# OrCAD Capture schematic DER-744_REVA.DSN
size B; title: DER 744 Rev A
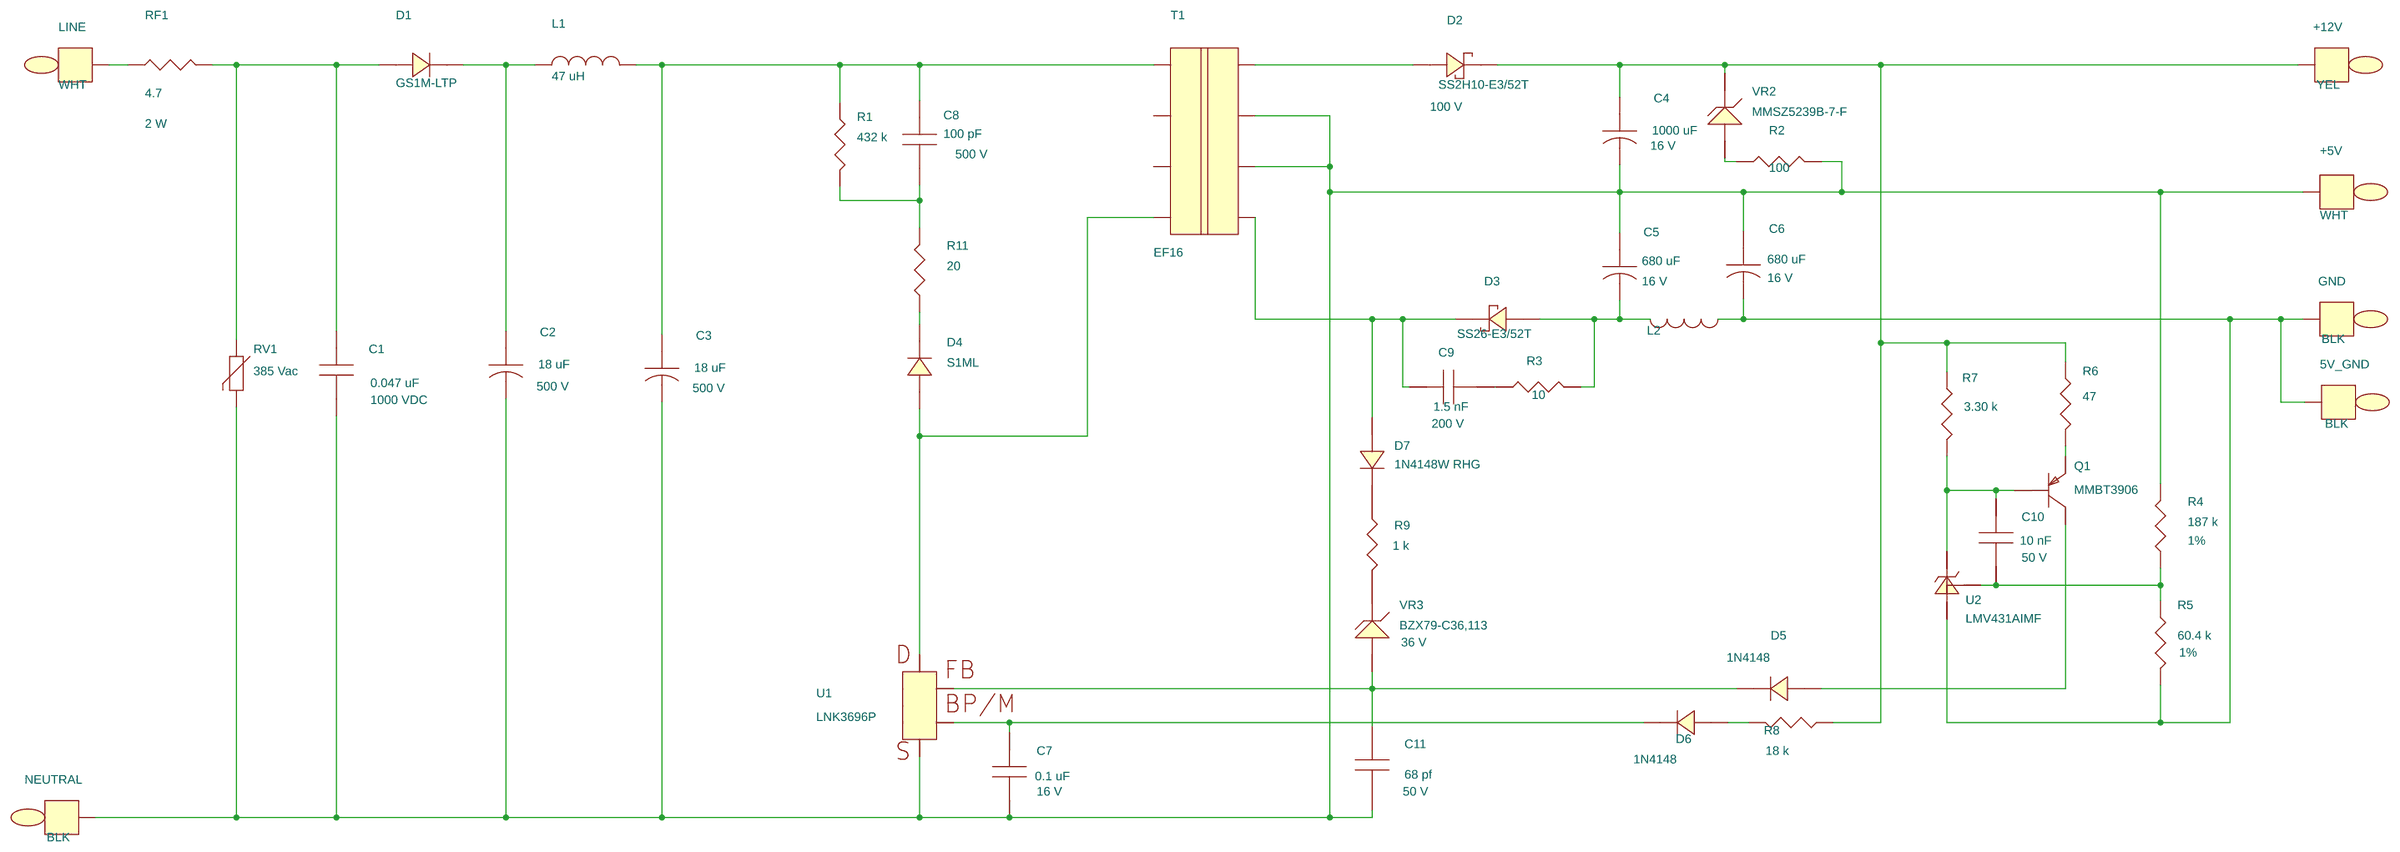
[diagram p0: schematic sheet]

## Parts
5V_GND  BLK  [pitpkeystone100x100]
+5V  WHT  [pitpkeystone100x100]
+12V  YEL  [pitpkeystone100x100]
C1  0.047 uF  [pinpcaprad18x6ls15mm040]
C2  18 uF  [pipolcapclyd630ls300040]
C3  18 uF  [pipolcapclyd630ls300040]
C4  1000 uF  [pipolcapclyd320ls140030]
C5  680 uF  [pi_polcap_d8h22ls3p5mmd030H]
C6  680 uF  [pi_polcap_d8h22ls3p5mmd030H]
C7  0.1 uF  [pismc0805]
C8  100 pF  [pismc1206]
C9  1.5 nF  [pismc0805]
C10  10 nF  [pismc0805]
C11  68 pf  [pismc0805]
D1  GS1M-LTP  [pismdo214ac12]
D2  SS2H10-E3/52T  [pismsmb]
D3  SS26-E3/52T  [pismdo214ac12]
D4  S1ML  [pi_sm_sod-123_12]
D5  1N4148  [pidv200x080x030do35]
D6  1N4148  [pidv200x080x030do35]
D7  1N4148W RHG  [pi_sm_sod-123_12]
GND  BLK  [pitpkeystone100x100]
L1  47 uH  [pichoketokinvd345h453ls197d030]
L2  50 Ohm @ 100MHz  [pismr1206]
LINE  WHT  [pitpkeystone125x125]
NEUTRAL  BLK  [pitpkeystone125x125]
Q1  MMBT3906  [pismsot23123_1]
R1  432 k  [pismr1206]
R2  100  [pismr0805]
R3  10  [pismr0805]
R4  187 k  [pi14wvresd100ls100d030]
R5  60.4 k  [pismr0805]
R6  47  [pismr0805]
R7  3.30 k  [pismr0805]
R8  18 k  [pismr0805]
R9  1 k  [pismr0805]
R11  20  [pismr1206]
RF1  4.7  [PI_2W_VRES240LS200D040]
RV1  385 Vac  [pi_disc_530x315ls295x70d040]
T1  EF16  [pibobbinEF16V8P]
U1  LNK3696P  [piicdip8cshort5678]
U2  LMV431AIMF  [pismsot23132]
VR2  MMSZ5239B-7-F  [pi_sm_sod-123_12]
VR3  BZX79-C36,113  [pidv200x080x030do35]

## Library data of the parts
5V_GND GND = TESTPOINT: Part Number: 35-00079-00
+5V = TESTPOINT: Part Number: 35-00081-00
+12V = TESTPOINT: Part Number: 35-00404-00
C1 = CAP_NP: Disp_Voltage: 1000 VDC; Part Number: 20-09149-00; Voltage: 1000 VDC (440VAC)
C2 C3 = CAP_POL: Disp_Voltage: 500 V; Part Number: 20-09150-00; Voltage: 500 V
C4 = CAP_POL: ALT_SYMBOLS: pipolcapclyd320ls140d30h750; Disp_Voltage: 16 V; FPLIST: pipolcapclyd320ls140030,pipolcapclyd320ls140d30h750; Part Number: 20-08710-00; Voltage: 16 V
C5 C6 = CAP_POL: ALT_SYMBOLS: pi_polcap_d8ls3p5mmd030; Disp_Voltage: 16 V; FPLIST: pi_polcap_d8h22ls3p5mmd030H,pi_polcap_d8ls3p5mmd030; Part Number: 20-09148-00; Voltage: 16V
C7 = CAP_NP: Disp_Voltage: 16 V; Part Number: 20-09164-00; Voltage: 16 V
C8 = CAP_NP: Disp_Voltage: 500 V; Part Number: 20-09163-00; Voltage: 500 V
C9 = CAP_NP: Disp_Voltage: 200 V; Part Number: 20-01150-00; Voltage: 200 V
C10 = CAP_NP: Disp_Voltage: 50 V; Part Number: 20-00965-00; Voltage: 50 V
C11 = CAP_NP: Disp_Voltage: 50 V; Part Number: 24-08976-00; Voltage: 50 V
D1 = DIODE: Part Number: 15-01111-00
D2 = DIODE_SCHOTTKY: Disp_Voltage: 100 V; Part Number: 15-00995-00
D3 = DIODE_SCHOTTKY: FPLIST: pismdo214aa12,pismdo214ac12; Part Number: 15-00366-00
D4 = DIODE: Part Number: 15-01027-00
D5 D6 = DIODE: ALT_SYMBOLS: pidax375x070030do35,pidv100x080x030do35; FPLIST: pidv200x080x030do35,pidax375x070030do35,pidv100x080x030do35; Part Number: 15-00083-00
D7 = DIODE: ALT_SYMBOLS: pi_sm_sod-123_12_1; FPLIST: pi_sm_sod-123_12,pi_sm_sod-123_12_1; Part Number: 15-01269-00
L1 = INDUCTOR: Part Number: 30-04098-00
L2 = INDUCTOR_BEAD: Part Number: 30-00491-00
LINE = TESTPOINT: Part Number: 35-00044-00
NEUTRAL = TESTPOINT: Part Number: 35-00042-00
Q1 = PNP_BEC: Part Number: 55-00049-00
R1 = R: Disp_Tol: 1%; Part Number: 05-00446-00
R2 = R: Part Number: 05-01495-00
R3 = R: Part Number: 05-01471-00
R4 = R: ALT_SYMBOLS: pi14wvresd100ls200d030,pi14wresd100ls400d030,pi14wresd100ls500d030; Disp_Tol: 1%; FPLIST: pi14wvresd100ls100d030,pi14wvresd100ls200d030,pi14wresd100ls400d030,pi14wresd100ls500d030; Part Number: 05-02194-00
R5 = R: Disp_Tol: 1%; Part Number: 05-00759-00
R6 = R: Part Number: 05-01487-00
R7 = R: Disp_Tol: 1%; Part Number: 05-05369-00
R8 = R: Part Number: 05-01549-00
R9 = R: Part Number: 05-01519-00
R11 = R: Part Number: 05-01311-00
RF1 = R: ALT_SYMBOLS: pi_2w_res6mmls15mmd040; Disp_Power: 2 W; FPLIST: PI_2W_VRES240LS200D040,pi_2w_res6mmls15mmd040; Part Number: 05-05550-00
RV1 = VARISTOR: ALT_SYMBOLS: pi_np_ycap_rad540ls400d040_h,pi_2w_resd145ls455d040; FPLIST: pi_disc_530x315ls295x70d040,pi_np_ycap_rad540ls400d040_h,pi_2w_resd145ls455d040; Part Number: 85-00021-00
T1 = BEF16_8PINS_GENERIC: Part Number: 25-01138-00
U1 = LNK3696: Part Number: 10-01089-00
U2 = TL431_SOT-23_RCA: Part Number: 45-00019-00
VR2 = DIODE_ZENER: Part Number: 15-01087-00
VR3 = DIODE_ZENER: ALT_SYMBOLS: pidax375x070030do35; Disp_Voltage: 36 V; FPLIST: pidv200x080x030do35,pidax375x070030do35; Part Number: 15-00270-00

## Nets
N00739: C7.1 D6.1 U1.1(BP/M)
N00834: D4.2 T1.4 U1.4(D)
N00928: C3.1 C8.1 L1.2 R1.1 T1.1
N01202: C8.2 R1.2 R11.2
N01422: C2.1 D1.1 L1.1
N01526: +5V.1 C1.2 C2.2 C3.2 C4.2 C5.1 C6.1 C7.2 C11.2 NEUTRAL.1 R2.2 R4.2 RV1.2 T1.6 T1.7 U1.5(S)
N01677: C1.1 D1.2 RF1.2 RV1.1
N02556: LINE.1 RF1.1
N02791: +12V.1 C4.1 D2.1 R6.1 R7.1 R8.1 VR2.1
N02906: C9.2 R3.1
N02910: C5.2 D3.2 L2.2 R3.2
N02953: C9.1 D3.1 D7.2 T1.5
N03528: 5V_GND.1 C6.2 GND.1 L2.1 R5.2 U2.3(A)
N03748: R2.1 VR2.2
N05482: C10.1 Q1.1(BASE) R7.2 U2.2(C)
N05581: C10.2 R4.1 R5.1 U2.1(VREF)
N08747: Q1.2(EMITTER) R6.2
N09276: C11.1 D5.1 U1.2(FB) VR3.2
N12197: D5.2 Q1.3(COLLECTOR)
N18239: D6.2 R8.2
N20828: D2.2 T1.8
N26989: D4.1 R11.1
N33471: D7.1 R9.1
N33472: R9.2 VR3.1

Not connected (* = marked no-connect by the designer): T1 2 3; U1 6(S6) 7(S7) 8(S8)
